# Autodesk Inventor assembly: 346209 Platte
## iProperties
Created: 2006-10
Part Number: 346209 Platte
Document SubType Name: Assembly
Designer: OSchmidt
Description: Seitenteil
Cost Center: 2,13 kg
Authority: 271335 mm^3
Mass: 2129.98 g
Surface Area: 676.195 cm^2
Volume: 271.335 cm^3
Density: 7.85 g/cm^3
SaveDate: 2006-11-06
SaveTime: 22:01
TotalMass: 2,13 kg
TotalVolume: 271335 mm^3
Author: Natti_01
